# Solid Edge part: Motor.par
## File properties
Author: CADCIM
Template: NORMENG.PAR
Last saved by: Cadcim
Revision: 6
Application: Solid Edge
Accuracy: 0.99
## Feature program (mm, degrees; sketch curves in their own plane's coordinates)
sketch for "unnamed Protrusion 1" plane through (0, 0, 0) normal (0, -1, 0) x-axis (1, 0, 0)
  line (-152.4, 0) -> (152.4, 0)
  line (152.4, 0) -> (83.1942, 183.7359)
  line (-152.4, 0) -> (-83.1942, 183.7359)
  dimension (linear) = 152.4
extrude "unnamed Protrusion 1" add finite 165.1 along -normal
sketch for "ExtrudedProtrusion_2" plane through (0, 165.1, 120.65) normal (0, 1, 0) x-axis (-1, 0, 0)
  circle centre (0, 31.75) radius 88.9
extrude "ExtrudedProtrusion_2" add finite 57.15 along +normal
sketch for "ExtrudedProtrusion_3" plane through (0, 222.25, 152.4) normal (0, 1, 0) x-axis (-1, 0, 0)
  circle centre (0, 0) radius 127
extrude "ExtrudedProtrusion_3" add finite 12.7 along +normal
sketch for "ExtrudedProtrusion_4" plane through (0, 222.25, 152.4) normal (0, -1, 0) x-axis (1, 0, 0)
  line (-76.2, 25.4) -> (76.2, 25.4)
  line (76.2, 25.4) -> (76.2, 152.4)
  line (76.2, 152.4) -> (-76.2, 152.4)
  line (-76.2, 152.4) -> (-76.2, 25.4)
  dimension (linear) = 76.2
  dimension (linear) = 76.2
extrude "ExtrudedProtrusion_4" add finite 203.2 along +normal
sketch for "unnamed Cutout 1" plane through (0, 19.05, 251.4953) normal (0, -1, 0) x-axis (1, 0, 0)
  line (-76.2, 41.8747) -> (-63.5, 41.8747)
  line (-63.5, 41.8747) -> (-63.5, 30.4447)
  line (-63.5, 30.4447) -> (-76.2, 30.4447)
  line (-76.2, 30.4447) -> (-76.2, 41.8747)
  dimension (linear) = 76.2
  dimension (linear) = 76.2
  dimension (linear) = 63.5
extrude "unnamed Cutout 1" cut along +normal
pattern "unnamed Pattern 1" of "unnamed Cutout 1"
extrude "unnamed Cutout 2" cut
extrude "unnamed Cutout 3" cut
extrude "unnamed Cutout 4" cut
extrude "unnamed Cutout 5" cut
extrude "unnamed Cutout 6" cut
extrude "unnamed Cutout 7" cut
extrude "unnamed Cutout 8" cut
sketch for "Hole_1" plane through (0, 234.95, 152.4) normal (0, 1, 0) x-axis (-1, 0, 0)
  hole centre (0, 0) bore radius 76.2
hole "Hole_1" diameter 152.4 finite
sketch for "Hole_2" plane through (0, 0, 120.65) normal (0, -1, 0) x-axis (1, 0, 0)
  hole centre (0, 31.75) bore radius 19.05
hole "Hole_2" diameter 38.1 through
sketch for "Hole_3" plane through (0, 234.95, 152.4) normal (0, 1, 0) x-axis (-1, 0, 0)
  hole centre (0, -107.95) bore radius 9.525
hole "Hole_3" diameter 19.05 through
pattern "unnamed Pattern 2" of "Hole_3"
pattern "unnamed Pattern 3"
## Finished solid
Body 1: solid body, 60 faces, 151 edges, 90 vertices.
  Faces by surface: plane 53, cylinder 7
  Edges by curve: line 126, circle 25
Bounding box of the edges (mm): 304.800 x 234.950 x 304.800, from (-152.4, 0, 0) to (152.4, 234.95, 304.8).
Cylindrical faces by radius (mm): R9.525 x3, R19.05 x1, R76.2 x1, R88.9 x1, R127 x1
Planar faces by outward normal: +x 9, +y 8, +z 9, -x 9, -y 7, -z 9, oblique 2
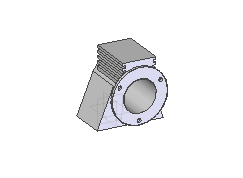
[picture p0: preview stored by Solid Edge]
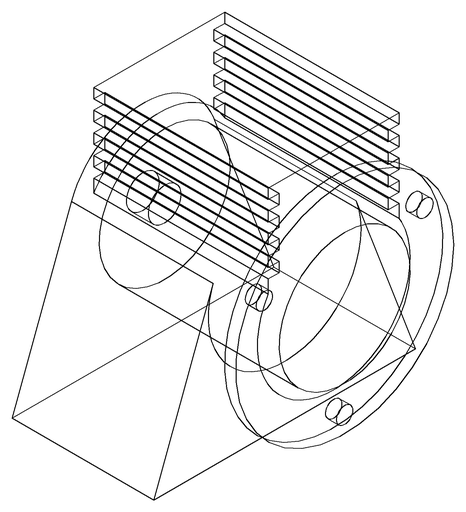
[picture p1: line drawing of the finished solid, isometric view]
